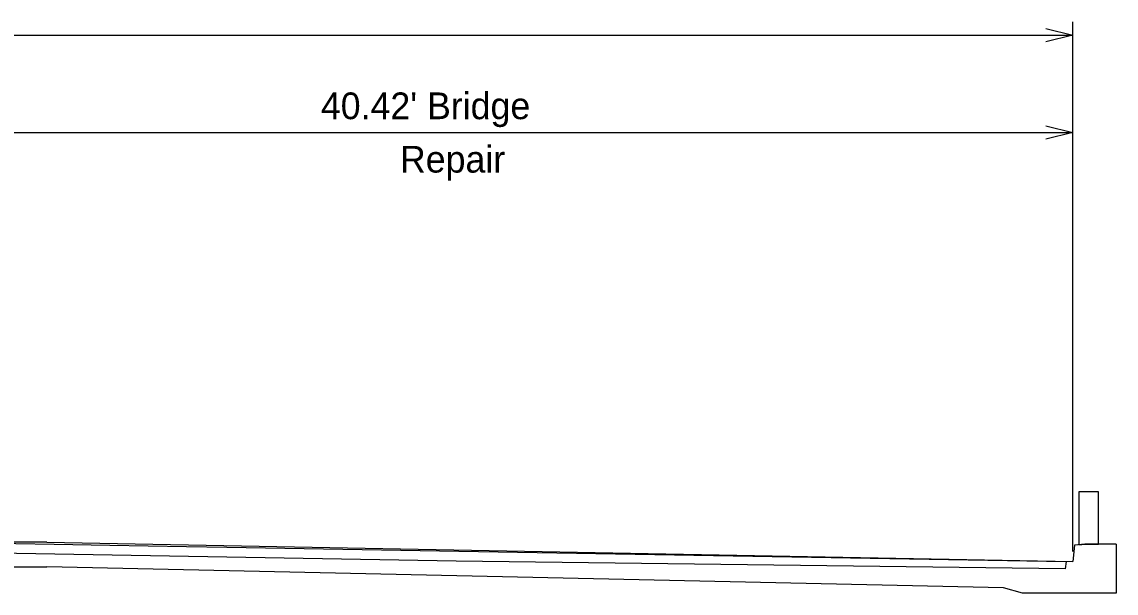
# Model space of a CAD drawing. Extents: x 8771 to 81668, y 6145 to 11018.
# Drawn here: x 11732 to 12662, y 6145 to 6631 of the extents above; entities that cross this region are included whole.
import ezdxf

# ---------------------------------------------------------------- set-up
doc = ezdxf.new("R2010")
doc.units = 0
for name, color, linetype in [('dsnCellElements', 7, 'Continuous'), ('DsnShtRevisedText', 7, 'Continuous'), ('ShtPlotIdentification', 7, 'Continuous')]:
    doc.layers.add(name, color=color, linetype=linetype)

msp = doc.modelspace()

# ---------------------------------------------------------------- linework, layer by layer
at = {"layer": 'dsnCellElements'}
for p, q in [((12624.93, 6187.4), (12624.93, 6631.02)), ((10720.67, 6619.67), (12624.93, 6619.67)), ((11672.8, 6536.96), (12624.93, 6536.96)), ((12624.93, 6180.83), (12624.93, 6467.02)), ((12630.16, 6186.52), (12635.36, 6187.06)), ((12635.36, 6187.06), (12646.82, 6187.06)), ((10779.45, 6163.72), (11752.89, 6167.9)), ((12566.15, 6149.87), (11752.89, 6167.9)), ((12582.37, 6145.43), (12566.15, 6149.87))]:
    msp.add_line(p, q, dxfattribs=at)
for points in [[(12602.22, 6625.35), (12624.93, 6619.67), (12602.22, 6613.99)], [(12602.22, 6542.63), (12624.93, 6536.96), (12602.22, 6531.28)], [(12646.82, 6187.06), (12646.82, 6231.53), (12630.16, 6231.53), (12630.16, 6186.52)], [(12661.85, 6187.06), (12661.85, 6145.43), (12582.37, 6145.43)], [(12661.85, 6187.06), (12635.36, 6187.06), (12626.37, 6186.12), (12624.93, 6172.27)]]:
    msp.add_lwpolyline(points, dxfattribs=at)
at = {"layer": 'DsnShtRevisedText'}
msp.add_lwpolyline([(12646.82, 6187.06), (12646.82, 6231.53), (12630.16, 6231.53), (12630.16, 6186.52)], dxfattribs=at)
at = {"layer": 'ShtPlotIdentification'}
for p, q in [((11752.89, 6188.81), (10720.67, 6186.12)), ((11752.89, 6188.81), (12624.93, 6172.27)), ((12100.92, 6172.61), (11669.91, 6180.13))]:
    msp.add_line(p, q, dxfattribs=at)
for points in [[(11669.92, 6184.61), (11669.95, 6188.59), (11681.96, 6188.39), (11700.48, 6188.07), (11726.48, 6187.63), (11759.21, 6187.07), (11806.37, 6186.26), (11871.61, 6185.15), (11906.06, 6184.56), (12103.22, 6181.19)], [(12103.22, 6181.19), (12619.26, 6172.37), (12618.57, 6166.09), (12100.92, 6172.61)]]:
    msp.add_lwpolyline(points, dxfattribs=at)

# ---------------------------------------------------------------- texts
at = {"layer": 'dsnCellElements'}
for s, height, p in [("40.42' Bridge", 22.7091, (11985.85, 6548.32)), ('Repair', 22.709, (12053.08, 6502.91))]:
    msp.add_text(s, height=height, dxfattribs=at).set_placement(p)

doc.saveas('drawing.dxf')
